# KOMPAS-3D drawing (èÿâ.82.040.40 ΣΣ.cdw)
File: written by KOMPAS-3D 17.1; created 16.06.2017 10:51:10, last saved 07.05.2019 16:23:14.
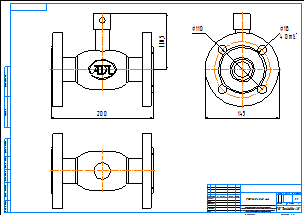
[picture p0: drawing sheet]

Sheet 1: A2, landscape

Title block, sheet 1: name: КШГ.82.040.40 фф; material: Внимание! Данный продукт является объектом авторского права ООО «Торговый Дом АДЛ». / Запрещается изменение, копирование, распространение / (в том числе путем копирования на другие сайты и ресурсы в Интернете) / или любое иное использование информации и объектов без предварительного / согласия правообладателя (ООО «Торговый Дом АДЛ»).; scale: 1:1; sheets: 1; organisation: ООО "Торговый дом АДЛ"; sheet format: A2; stored path: C:\Users\tra\Desktop\2д чертежи\Шаровые краны БИВАЛ\КШ_Бивал_серия_82_85\KOMPAS 2D\КШГ.82.040.40 фф.cdw

Views: Спереди 1, Проекционный вид 2, Проекционный вид 3
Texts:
  Klimkovich
  ADL
Dimensions and other numbers on the sheet: 200; 110,5; 110; 18; 4 Отв.; 145; 1:1; 1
